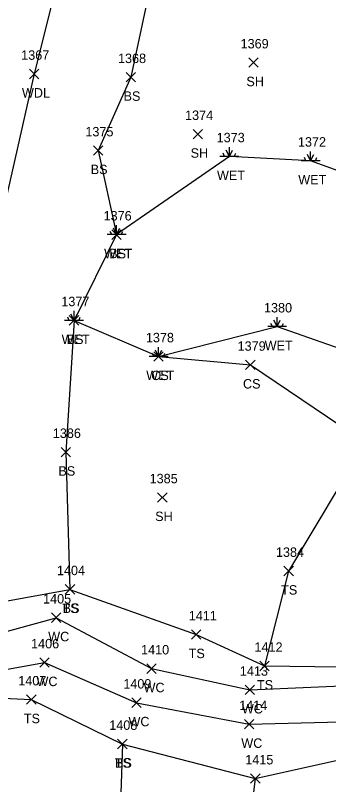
# Model space of a CAD drawing. Extents: x 1551995 to 1555700, y 777276 to 783130.
# Drawn here: x 1554908 to 1554974.4, y 777646.9 to 777809.8 of the extents above; entities that cross this region are included whole.
import ezdxf

# ---------------------------------------------------------------- set-up
doc = ezdxf.new("R2010")
doc.units = 0
for name, color, linetype in [('L_A', 7, 'Continuous'), ('L_I', 7, 'Continuous'), ('L_TIC', 7, 'Continuous'), ('LAWA', 7, 'Continuous'), ('LAWE', 7, 'Continuous'), ('LELB', 7, 'Continuous'), ('LWET', 7, 'Continuous')]:
    doc.layers.add(name, color=color, linetype=linetype)

msp = doc.modelspace()

# ---------------------------------------------------------------- linework, layer by layer
at = {"layer": 'L_TIC'}
for points in [[(1554957.48, 777798.8), (1554959.48, 777800.8)], [(1554959.48, 777798.8), (1554957.48, 777800.8)], [(1554910.99, 777796.39), (1554912.99, 777798.39)], [(1554912.99, 777796.39), (1554910.99, 777798.39)], [(1554931.5, 777795.7), (1554933.5, 777797.7)], [(1554933.5, 777795.7), (1554931.5, 777797.7)], [(1554945.66, 777783.65), (1554947.66, 777785.65)], [(1554947.66, 777783.65), (1554945.66, 777785.65)], [(1554924.54, 777780.17), (1554926.54, 777782.17)], [(1554926.54, 777780.17), (1554924.54, 777782.17)], [(1554928.46, 777762.36), (1554930.46, 777764.36)], [(1554930.46, 777762.36), (1554928.46, 777764.36)], [(1554919.45, 777744.2), (1554921.45, 777746.2)], [(1554921.45, 777744.2), (1554919.45, 777746.2)], [(1554937.36, 777736.56), (1554939.36, 777738.56)], [(1554939.36, 777736.56), (1554937.36, 777738.56)], [(1554956.8, 777734.77), (1554958.8, 777736.77)], [(1554958.8, 777734.77), (1554956.8, 777736.77)], [(1554917.7, 777716.31), (1554919.7, 777718.31)], [(1554919.7, 777716.31), (1554917.7, 777718.31)], [(1554938.15, 777706.7), (1554940.15, 777708.7)], [(1554940.15, 777706.7), (1554938.15, 777708.7)], [(1554964.91, 777691.12), (1554966.91, 777693.12)], [(1554966.91, 777691.12), (1554964.91, 777693.12)], [(1554918.59, 777687.24), (1554920.59, 777689.24)], [(1554920.59, 777687.24), (1554918.59, 777689.24)], [(1554918.59, 777687.24), (1554920.59, 777689.24)], [(1554920.59, 777687.24), (1554918.59, 777689.24)], [(1554915.66, 777681.24), (1554917.66, 777683.24)], [(1554917.66, 777681.24), (1554915.66, 777683.24)], [(1554945.32, 777677.67), (1554947.32, 777679.67)], [(1554947.32, 777677.67), (1554945.32, 777679.67)], [(1554913.18, 777671.74), (1554915.18, 777673.74)], [(1554915.18, 777671.74), (1554913.18, 777673.74)], [(1554935.86, 777670.45), (1554937.86, 777672.45)], [(1554937.86, 777670.45), (1554935.86, 777672.45)], [(1554959.8, 777671.01), (1554961.8, 777673.01)], [(1554961.8, 777671.01), (1554959.8, 777673.01)], [(1554959.8, 777671.01), (1554961.8, 777673.01)], [(1554961.8, 777671.01), (1554959.8, 777673.01)], [(1554956.7, 777665.95), (1554958.7, 777667.95)], [(1554958.7, 777665.95), (1554956.7, 777667.95)], [(1554910.4, 777663.89), (1554912.4, 777665.89)], [(1554912.4, 777663.89), (1554910.4, 777665.89)], [(1554932.67, 777663.23), (1554934.67, 777665.23)], [(1554934.67, 777663.23), (1554932.67, 777665.23)], [(1554956.57, 777658.67), (1554958.57, 777660.67)], [(1554958.57, 777658.67), (1554956.57, 777660.67)], [(1554929.69, 777654.48), (1554931.69, 777656.48)], [(1554931.69, 777654.48), (1554929.69, 777656.48)], [(1554929.69, 777654.48), (1554931.69, 777656.48)], [(1554931.69, 777654.48), (1554929.69, 777656.48)], [(1554957.85, 777647.16), (1554959.85, 777649.16)], [(1554959.85, 777647.16), (1554957.85, 777649.16)], [(1554957.85, 777647.16), (1554959.85, 777649.16)], [(1554959.85, 777647.16), (1554957.85, 777649.16)]]:
    msp.add_lwpolyline(points, dxfattribs=at)
at = {"layer": 'LAWA'}
msp.add_lwpolyline([(1554924.17, 777845.95), (1554911.99, 777797.39), (1554901.73, 777752.36), (1554891.43, 777715.92), (1554886.53, 777681.63), (1554885.54, 777676.35), (1554886.43, 777672.72), (1554885.1, 777668.28), (1554876.24, 777640.92), (1554874.65, 777639.02), (1554865.05, 777604.93), (1554832.26, 777556.58), (1554828.6, 777545), (1554825.77, 777534.55), (1554825.26, 777531.03), (1554824.11, 777527.47), (1554817.13, 777514.36), (1554810.78, 777500.84), (1554797.7, 777469.38), (1554813.54, 777462.7)], dxfattribs=at)
at = {"layer": 'LAWE'}
for points in [[(1554896.13, 777669.49), (1554914.18, 777672.74), (1554933.67, 777664.23), (1554957.57, 777659.67), (1554982.43, 777660.34), (1555001.98, 777663.11), (1555028.12, 777669.98), (1555046.42, 777677.46), (1555063.93, 777692.17), (1555074.78, 777708.2), (1555088.15, 777717.7), (1555098.22, 777729.19), (1555108.92, 777737.75), (1555125.5, 777739.97), (1555133.42, 777752.91), (1555147.36, 777756.73)], [(1554896.13, 777669.49), (1554895.5, 777676.41), (1554916.66, 777682.24), (1554936.86, 777671.45), (1554957.7, 777666.95), (1554983.51, 777668.08)]]:
    msp.add_lwpolyline(points, dxfattribs=at)
at = {"layer": 'LELB'}
for points in [[(1555000.87, 778001.08), (1555009.49, 778000.82), (1555019.32, 777999.5), (1555016.45, 777976.79), (1555007.25, 777941.96), (1555001.69, 777908.63), (1554997.48, 777871.9), (1554988.59, 777829.9), (1554987.68, 777801.59), (1554990.67, 777771.72), (1554987.39, 777735.48), (1554982.18, 777719.34), (1554965.91, 777692.12), (1554960.8, 777672.01)], [(1554989.73, 777998.18), (1554984.34, 777975.58), (1554972.66, 777949.31), (1554962.52, 777914.84), (1554954.2, 777880.1), (1554942.29, 777842.69), (1554932.5, 777796.7), (1554925.54, 777781.17), (1554929.46, 777763.36)], [(1554920.45, 777745.2), (1554918.7, 777717.31), (1554919.59, 777688.24)], [(1554938.36, 777737.56), (1554957.8, 777735.77), (1554982.18, 777719.34), (1554998.86, 777694.95), (1555004.18, 777677.14)], [(1554886.53, 777681.63), (1554898.11, 777684.35), (1554919.59, 777688.24), (1554946.32, 777678.67), (1554960.8, 777672.01), (1554976.86, 777671.82)], [(1554873.83, 777672.65), (1554885.1, 777668.28), (1554896.47, 777665.61), (1554911.4, 777664.89), (1554930.69, 777655.48), (1554958.85, 777648.16), (1554982.59, 777653.45), (1554998.31, 777654.1)], [(1554930.69, 777655.48), (1554929.45, 777618.01), (1554915.79, 777577.44), (1554889.14, 777548.05), (1554880.78, 777507.43)], [(1554958.85, 777648.16), (1554954.89, 777615.53), (1554962.82, 777573.82), (1554966.58, 777524.51), (1554944.93, 777477.76)]]:
    msp.add_lwpolyline(points, dxfattribs=at)
at = {"layer": 'LWET'}
for p, q in [((1554953.35, 777779.92), (1554953.35, 777781.92)), ((1554955.35, 777779.92), (1554951.35, 777779.92)), ((1554952.35, 777779.92), (1554952.02, 777780.59)), ((1554953.35, 777779.92), (1554952.69, 777781.26)), ((1554953.35, 777779.92), (1554954.02, 777781.26)), ((1554954.35, 777779.92), (1554954.69, 777780.59)), ((1554970.57, 777779), (1554969.91, 777780.34)), ((1554970.57, 777779), (1554970.57, 777781)), ((1554970.57, 777779), (1554971.24, 777780.34)), ((1554972.57, 777779), (1554968.57, 777779)), ((1554969.57, 777779), (1554969.24, 777779.67)), ((1554971.57, 777779), (1554971.91, 777779.67)), ((1554929.46, 777763.36), (1554929.46, 777765.36)), ((1554928.46, 777763.36), (1554928.12, 777764.03)), ((1554929.46, 777763.36), (1554928.79, 777764.7)), ((1554929.46, 777763.36), (1554930.12, 777764.7)), ((1554930.46, 777763.36), (1554930.79, 777764.03)), ((1554931.46, 777763.36), (1554927.46, 777763.36)), ((1554920.45, 777745.2), (1554920.45, 777747.2)), ((1554919.45, 777745.2), (1554919.11, 777745.87)), ((1554920.45, 777745.2), (1554919.78, 777746.53)), ((1554920.45, 777745.2), (1554921.11, 777746.53)), ((1554921.45, 777745.2), (1554921.78, 777745.87)), ((1554963.47, 777743.88), (1554963.47, 777745.88)), ((1554922.45, 777745.2), (1554918.45, 777745.2)), ((1554962.47, 777743.88), (1554962.13, 777744.55)), ((1554963.47, 777743.88), (1554962.8, 777745.22)), ((1554963.47, 777743.88), (1554964.13, 777745.22)), ((1554964.47, 777743.88), (1554964.8, 777744.55)), ((1554965.47, 777743.88), (1554961.47, 777743.88)), ((1554938.36, 777737.56), (1554938.36, 777739.56)), ((1554940.36, 777737.56), (1554936.36, 777737.56)), ((1554937.36, 777737.56), (1554937.03, 777738.23)), ((1554938.36, 777737.56), (1554937.69, 777738.89)), ((1554938.36, 777737.56), (1554939.03, 777738.89)), ((1554939.36, 777737.56), (1554939.69, 777738.23))]:
    msp.add_line(p, q, dxfattribs=at)
msp.add_lwpolyline([(1554990.67, 777771.72), (1554970.57, 777779), (1554953.35, 777779.92), (1554929.46, 777763.36), (1554920.45, 777745.2), (1554938.36, 777737.56), (1554963.47, 777743.88), (1554987.39, 777735.48)], dxfattribs=at)

# ---------------------------------------------------------------- texts
at = {"layer": 'L_A'}
for s, p in [('SH', (1554956.96, 777794.8)), ('WDL', (1554909.41, 777792.39)), ('BS', (1554930.94, 777791.7)), ('SH', (1554945.15, 777779.65)), ('BS', (1554923.98, 777776.17)), ('WET', (1554950.73, 777774.92)), ('WET', (1554967.95, 777774)), ('WET', (1554926.83, 777758.36)), ('BS', (1554927.9, 777758.36)), ('WET', (1554917.82, 777740.2)), ('BS', (1554918.89, 777740.2)), ('WET', (1554960.84, 777738.88)), ('WET', (1554935.74, 777732.56)), ('CS', (1554936.8, 777732.56)), ('CS', (1554956.24, 777730.77)), ('BS', (1554917.14, 777712.31)), ('SH', (1554937.64, 777702.7)), ('TS', (1554964.32, 777687.12)), ('TS', (1554918, 777683.24)), ('BS', (1554918.03, 777683.24)), ('WC', (1554914.97, 777677.24)), ('TS', (1554944.73, 777673.67)), ('WC', (1554912.49, 777667.74)), ('TS', (1554959.2, 777667.01)), ('TS', (1554959.2, 777667.01)), ('WC', (1554935.17, 777666.45)), ('WC', (1554956.01, 777661.95)), ('TS', (1554909.81, 777659.89)), ('WC', (1554931.98, 777659.23)), ('WC', (1554955.88, 777654.67)), ('TS', (1554929.1, 777650.48)), ('BS', (1554929.13, 777650.48))]:
    msp.add_text(s, height=2, dxfattribs=at).set_placement(p)
at = {"layer": 'L_I'}
for s, p in [('1369', (1554955.73, 777802.8)), ('1367', (1554909.25, 777800.39)), ('1368', (1554929.76, 777799.7)), ('1374', (1554943.97, 777787.65)), ('1375', (1554922.85, 777784.17)), ('1373', (1554950.66, 777782.92)), ('1372', (1554967.88, 777782)), ('1376', (1554926.71, 777766.36)), ('1376', (1554926.71, 777766.36)), ('1377', (1554917.75, 777748.2)), ('1377', (1554917.75, 777748.2)), ('1380', (1554960.69, 777746.88)), ('1378', (1554935.67, 777740.56)), ('1378', (1554935.67, 777740.56)), ('1379', (1554955.1, 777738.77)), ('1386', (1554915.95, 777720.31)), ('1385', (1554936.46, 777710.7)), ('1384', (1554963.22, 777695.12)), ('1404', (1554916.82, 777691.24)), ('1404', (1554916.82, 777691.24)), ('1405', (1554913.89, 777685.24)), ('1411', (1554944.76, 777681.67)), ('1406', (1554911.35, 777675.74)), ('1410', (1554934.65, 777674.45)), ('1412', (1554958.67, 777675.01)), ('1412', (1554958.67, 777675.01)), ('1413', (1554955.58, 777669.95)), ('1407', (1554908.63, 777667.89)), ('1409', (1554930.89, 777667.23)), ('1414', (1554955.44, 777662.67)), ('1408', (1554927.91, 777658.48)), ('1408', (1554927.91, 777658.48)), ('1415', (1554956.72, 777651.16)), ('1415', (1554956.72, 777651.16))]:
    msp.add_text(s, height=2, dxfattribs=at).set_placement(p)

doc.saveas('drawing.dxf')
